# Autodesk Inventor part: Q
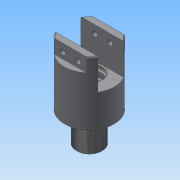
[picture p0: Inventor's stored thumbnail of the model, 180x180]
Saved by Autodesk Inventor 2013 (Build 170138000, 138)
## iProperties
Created: 2019-02
Part Number: Q
Material: 일반
Document SubType Name: Modeling
Designer: Administrator
Density: 1 g/cm^3
Author: Administrator
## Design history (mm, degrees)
sketch "스케치1"
  geometry: C1 r 29 at (0, 0); 1 further point
  constraints: 1 centre point, 1 coincident
  dimensions: "d0" = 58 diameter of C1
extrude "돌출1" new body sketch "스케치1" distance "d1" = 74; taper "d2" = 0 deg
sketch "스케치2"
  geometry: C1 r 29 at (0, 0) reference; C2 r 13 at (0, 0)
  constraints: 1 centre point, 1 coincident
  dimensions: "d3" = 26 diameter of C2
extrude "돌출2" join sketch "스케치2" distance "d4" = 5; taper "d5" = 0 deg
sketch "스케치3"
  geometry: C1 r 13 at (0, 0) reference; C2 r 15 at (0, 0)
  constraints: 1 centre point, 1 coincident
  dimensions: "d6" = 30 diameter of C2
extrude "돌출3" join sketch "스케치3" distance "d7" = 29; taper "d8" = 0 deg
feature "스레드1" dims "d9" = 10, "d10" = 0
chamfer "모따기1" distance "d11" = 1; stored, may be unused: second distance "d12" = 2, angle "d13" = 45 deg
sketch "스케치5"
  geometry: L1 (29, 74)-(-29, 74) reference; L2 (-29, 1)-(29, 1) reference; L3 (13, -5)-(15, -5) reference; L4 (15, -5)-(15, -34) reference; L5 (15, -34)-(-15, -34) reference; L6 (-15, -34)-(-15, -5) reference; L7 (-15, -5)-(-13, -5) reference; L8 (-13, -5)-(-13, 0) reference; L9 (-13, 0)-(-28, 0) reference; L10 (-28, 0)-(-29, 1) reference; L11 (-29, 1)-(-29, 74) reference; L12 (-29, 74)-(29, 74) reference; L13 (29, 74)-(29, 1) reference; L14 (29, 1)-(28, 0) reference; L15 (28, 0)-(13, 0) reference; L16 (13, 0)-(13, -5) reference; L17 (15, 74)-(-15, 74); L18 (-15, 74)-(-15, 38); L19 (-15, 38)-(15, 38); L20 (15, 38)-(15, 74); 3 further points
  constraints: 8 end point, 3 midpoint, 2 parallel, 1 coincident, 1 horizontal, 1 perpendicular
  dimensions: "d14" = 30 distance of L19.end L18.end; "d15" = 36 distance of L18.end L17.end
extrude "돌출4" cut sketch "스케치5" stored distance "d16" = 29; taper "d17" = 0 deg
sketch "스케치7"
  geometry: C1 r 15 at (0, 0) reference; 1 further point
  constraints: 1 coincident
hole "구멍1" sketch "스케치7" at (0, 0) diameter "d19" = 12.376; stored, may be unused: countersink angle "d23" = 90 deg, drill point angle "d25" = 118 deg; dims "d20" = 18, "d21" = 4, "d22" = 2, "d24" = 22
sketch "스케치10"
  geometry: C1 r 14 at (24.819, 15); A1 r 29 centre (24.819, 15) between (49.639, 0) and (49.639, 30) reference
  constraints: 1 centre point, 1 coincident
  dimensions: "d29" = 28 diameter of C1
extrude "돌출6" cut sketch "스케치10" distance "d30" = 27; taper "d31" = 0 deg
sketch "스케치11"
  geometry: L1 (17, 35.35)-(14, 35.35); L2 (14, 35.35)-(14, 30.65); L3 (14, 30.65)-(17, 30.65); L4 (17, 30.65)-(17, 35.35); L5 (13, -5)-(15, -5) reference; L6 (15, -5)-(15, -34) reference; L7 (15, -34)-(6.188, -34) reference; L8 (6.188, -34)-(6.188, -12) reference; L9 (6.188, -12)-(0, -8.282) reference; L10 (0, -8.282)-(-6.188, -12) reference; L11 (-6.188, -12)-(-6.188, -34) reference; L12 (-6.188, -34)-(-15, -34) reference; L13 (-15, -34)-(-15, -5) reference; L14 (-15, -5)-(-13, -5) reference; L15 (-13, -5)-(-13, 0) reference; L16 (-13, 0)-(-28, 0) reference; L17 (-28, 0)-(-29, 1) reference; L18 (-29, 1)-(-29, 38) reference; L19 (-29, 38)-(-14, 38) reference; L20 (-14, 38)-(-14, 11) reference; L21 (-14, 11)-(14, 11) reference; L22 (14, 11)-(14, 38) reference; L23 (14, 38)-(29, 38) reference; L24 (29, 38)-(29, 1) reference; L25 (29, 1)-(28, 0) reference; L26 (28, 0)-(13, 0) reference; L27 (13, 0)-(13, -5) reference; L28 (13, -5)-(15, -5) reference; L29 (15, -5)-(15, -34) reference; L30 (15, -34)-(6.188, -34) reference; L31 (6.188, -34)-(6.188, -12) reference; L32 (6.188, -12)-(0, -8.282) reference; L33 (0, -8.282)-(-6.188, -12) reference; L34 (-6.188, -12)-(-6.188, -34) reference; L35 (-6.188, -34)-(-15, -34) reference; L36 (-15, -34)-(-15, -5) reference; L37 (-15, -5)-(-13, -5) reference; L38 (-13, -5)-(-13, 0) reference; L39 (-13, 0)-(-28, 0) reference; L40 (-28, 0)-(-29, 1) reference; L41 (-29, 1)-(-29, 38) reference; L42 (-29, 38)-(-14, 38) reference; L43 (-14, 38)-(-14, 11) reference; L44 (-14, 11)-(14, 11) reference; L45 (14, 11)-(14, 38) reference; L46 (14, 38)-(29, 38) reference; L47 (29, 38)-(29, 1) reference; L48 (29, 1)-(28, 0) reference; L49 (28, 0)-(13, 0) reference; L50 (13, 0)-(13, -5) reference; L51 (13, -5)-(15, -5) reference; L52 (15, -5)-(15, -34) reference; L53 (15, -34)-(6.188, -34) reference; L54 (6.188, -34)-(6.188, -12) reference; L55 (6.188, -12)-(0, -8.282) reference; L56 (0, -8.282)-(-6.188, -12) reference; L57 (-6.188, -12)-(-6.188, -34) reference; L58 (-6.188, -34)-(-15, -34) reference; L59 (-15, -34)-(-15, -5) reference; L60 (-15, -5)-(-13, -5) reference; L61 (-13, -5)-(-13, 0) reference; L62 (-13, 0)-(-28, 0) reference; L63 (-28, 0)-(-29, 1) reference; L64 (-29, 1)-(-29, 38) reference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; 2 further points
  constraints: 8 end point, 2 parallel, 1 horizontal, 1 midpoint, 1 perpendicular, 1 point on line
  dimensions: "d32" = 3 distance of L3.end L2.end; "d33" = 4.7 distance of L2.end L1.end; "d34" = 5 distance from line of L23 point (17, 33)
revolve "회전1" sketch "스케치11" stored, may be unused: angle "d35" = 90 deg
sketch "스케치12"
  geometry: L1 (13, -5)-(15, -5) reference; L2 (15, -5)-(15, -34) reference; L3 (15, -34)-(6.188, -34) reference; L4 (6.188, -34)-(6.188, -12) reference; L5 (6.188, -12)-(0, -8.282) reference; L6 (0, -8.282)-(-6.188, -12) reference; L7 (-6.188, -12)-(-6.188, -34) reference; L8 (-6.188, -34)-(-15, -34) reference; L9 (-15, -34)-(-15, -5) reference; L10 (-15, -5)-(-13, -5) reference; L11 (-13, -5)-(-13, 0) reference; L12 (-13, 0)-(-28, 0) reference; L13 (-28, 0)-(-29, 1) reference; L14 (-29, 1)-(-29, 74) reference; L15 (-29, 74)-(-15, 74) reference; L16 (-15, 74)-(-15, 38) reference; L17 (-15, 38)-(-14, 38) reference; L18 (-14, 38)-(-14, 35.35) reference; L19 (-14, 35.35)-(-17, 35.35) reference; L20 (-17, 35.35)-(-17, 30.65) reference; L21 (-17, 30.65)-(-14, 30.65) reference; L22 (-14, 30.65)-(-14, 11) reference; L23 (-14, 11)-(14, 11) reference; L24 (14, 11)-(14, 30.65) reference; L25 (14, 30.65)-(17, 30.65) reference; L26 (17, 30.65)-(17, 35.35) reference; L27 (17, 35.35)-(14, 35.35) reference; L28 (14, 35.35)-(14, 38) reference; L29 (14, 38)-(15, 38) reference; L30 (15, 38)-(15, 74) reference; L31 (15, 74)-(29, 74) reference; L32 (29, 74)-(29, 1) reference; L33 (29, 1)-(28, 0) reference; L34 (28, 0)-(13, 0) reference; L35 (13, 0)-(13, -5) reference; L36 (17, 26.35)-(14, 26.35); L37 (14, 26.35)-(14, 21.65); L38 (14, 21.65)-(17, 21.65); L39 (17, 21.65)-(17, 26.35); L40 (16, 18)-(14, 18); L41 (14, 18)-(14, 11); L42 (14, 11)-(16, 11); L43 (16, 11)-(16, 18); L44 (0, -55.6)-(0, 95.6) reference; 3 further points
  constraints: 16 end point, 4 parallel, 2 horizontal, 2 midpoint, 2 perpendicular, 2 vertical alignment
  dimensions: "d36" = 3 distance of L38.end L37.end; "d37" = 4.7 distance of L37.end L36.end; "d38" = 9 distance of point (17, 24) point (17, 33); "d39" = 2 distance of L23.end L42.end; "d40" = 7 distance of L23.end L40.end
revolve "회전2" sketch "스케치12" stored, may be unused: angle "d41" = 90 deg
sketch "스케치13"
  geometry: C1 r 16 at (0, 0) reference; C2 r 4 at (0, 0)
  constraints: 1 centre point, 1 coincident
  dimensions: "d42" = 8 diameter of C2
extrude "돌출7" cut sketch "스케치13" stored distance "d43" = 27; taper "d44" = 0 deg
fillet "모깎기1" dims "d45" = 0.8
chamfer "모따기2" distance "d46" = 1; stored, may be unused: second distance "d47" = 2, angle "d48" = 45 deg
sketch "스케치14"
  geometry: L1 (-24.819, 15)-(24.819, 15) reference; L2 (-33.797, 22)-(45.283, 22); L3 (45.283, 22)-(45.283, 45.636); L4 (45.283, 45.636)-(-33.797, 45.636); L5 (-33.797, 45.636)-(-33.797, 22)
  constraints: 8 end point, 2 parallel, 1 horizontal, 1 perpendicular
  dimensions: "d49" = 7 distance between parallel lines of L2 L1; "d50" = 23.63573 distance of L4.end L2.start; "d51" = 79.0803 distance of L3.end L4.end
extrude "돌출8" cut sketch "스케치14" distance "d52" = 16; taper "d53" = 0 deg
sketch "스케치15"
  geometry: L1 (24.819, -15)-(-24.819, -15) reference; L2 (-30.704, -37.242)-(36.669, -37.242); L3 (36.669, -37.242)-(36.669, -22); L4 (36.669, -22)-(-30.704, -22); L5 (-30.704, -22)-(-30.704, -37.242)
  constraints: 8 end point, 2 parallel, 1 horizontal, 1 perpendicular
  dimensions: "d54" = 7 distance between parallel lines of L1 L4; "d55" = 15.24173 distance of L4.end L2.start
extrude "돌출9" cut sketch "스케치15" distance "d56" = 16; taper "d57" = 0 deg
sketch "스케치16"
  geometry: L1 (37.789, 0)-(0, 0) reference; C1 r 3 at (27.894, 9); C2 r 3 at (9.894, 9); 1 further point
  constraints: 2 centre point, 1 horizontal alignment
  dimensions: "d58" = 6 diameter of C1; "d59" = 6 diameter of C2; "d60" = 18 distance of C1.centre C2.centre; "d61" = 9 distance from line of C1.centre L1; "d62" = 9 horizontal distance of C2.centre point (18.894, 74)
extrude "돌출10" cut sketch "스케치16" stored distance "d63" = 16; taper "d64" = 0 deg
chamfer "모따기3" distance "d65" = 1; stored, may be unused: second distance "d66" = 2, angle "d67" = 45 deg
chamfer "모따기4" distance "d68" = 1; stored, may be unused: second distance "d69" = 2, angle "d70" = 45 deg
node "작업 평면1"
sketch "스케치17"
  geometry: L1 (5, 45)-(-5, 45); L2 (-5, 45)-(-5, 5); L3 (-5, 5)-(5, 5); L4 (5, 5)-(5, 45); L5 (28, 0)-(-28, 0) reference; 2 further points
  constraints: 8 end point, 2 parallel, 1 horizontal, 1 midpoint, 1 perpendicular, 1 vertical alignment
  dimensions: "d72" = 10 distance of L3.end L2.end; "d73" = 40 distance of L2.end L1.end; "d74" = 5 distance between parallel lines of L5 L3
extrude "돌출11" join sketch "스케치17" stored distance "d75" = 16; taper "d76" = 0 deg
sketch "스케치18"
  geometry: L1 (-5, -45)-(5, -45) reference; L2 (5, -45)-(5, -5) reference; 2 further points
  constraints: 1 other
  dimensions: "d77" = 20 distance from line of L1 point (0, -25); "d78" = 5 distance from line of L2 point (0, -25)
feature "엠보싱1" sketch "스케치18" dims "d79" = 0.5, "d80" = 0
chamfer "모따기5" distance "d81" = 1; stored, may be unused: second distance "d82" = 2, angle "d83" = 45 deg
node "솔리드1"
node "투영된 루프1"
node "절단 모서리 투영1"
node "절단 모서리 투영2"
node "절단 모서리 투영3"
node "절단 모서리 투영4"
node "절단 모서리 투영5"
